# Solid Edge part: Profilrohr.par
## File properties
Username: bmolnar
Dokumentum tartalom típus: 0
Author: bmolnar
Last saved by: bmolnar
Revision: 85
Sűrűség: 0,000 kg/m^3
Pontosság: 0,990
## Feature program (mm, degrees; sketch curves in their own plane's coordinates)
base feature "unnamed BaseFeature 1"
thread "unnamed Thread 1"
thread "Menet_2"  ThreadDepth = 5.5 mm
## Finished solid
Body 1: solid body, 127 faces, 307 edges, 198 vertices.
  Faces by surface: cylinder 57, plane 52, cone 16, torus 2
  Edges by curve: line 144, circle 142, spline 9, curve on surface 7, intersection 5
Bounding box of the edges (mm; curved faces can reach further): 30.000 x 34.000 x 78.000, from (-15, -15, 0) to (15, 19, 78).
Cylindrical faces by radius (mm): R0.3 x24, R0.65 x2, R1.85 x4, R2 x2, R2.067 x4, R2.35 x2, R2.8 x4, R3.75 x4, R8 x1, R8.95 x2, R9.1 x2, R9.5 x2, R20 x4
Conical faces (half-angle, radius in mm at the cone's reference point): 45 deg R2.317 x2, 45 deg R2.95 x4, 45 deg R3.9 x4, 45 deg R8.4 x2, 45 deg R9.2 x2, 45 deg R9.25 x2
Toroidal faces (ring radius, tube radius in mm): R9.4 r0.1 x2
Planar faces by outward normal: +x 6, +y 9, +z 9, -x 6, -y 5, -z 9, oblique 8
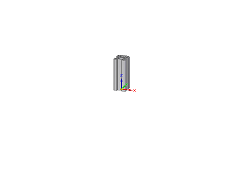
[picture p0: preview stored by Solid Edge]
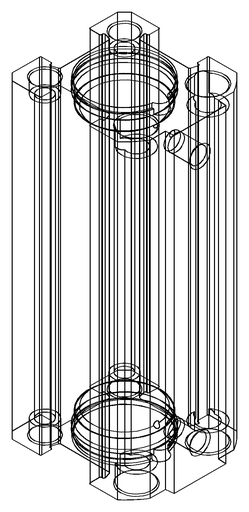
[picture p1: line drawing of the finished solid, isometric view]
